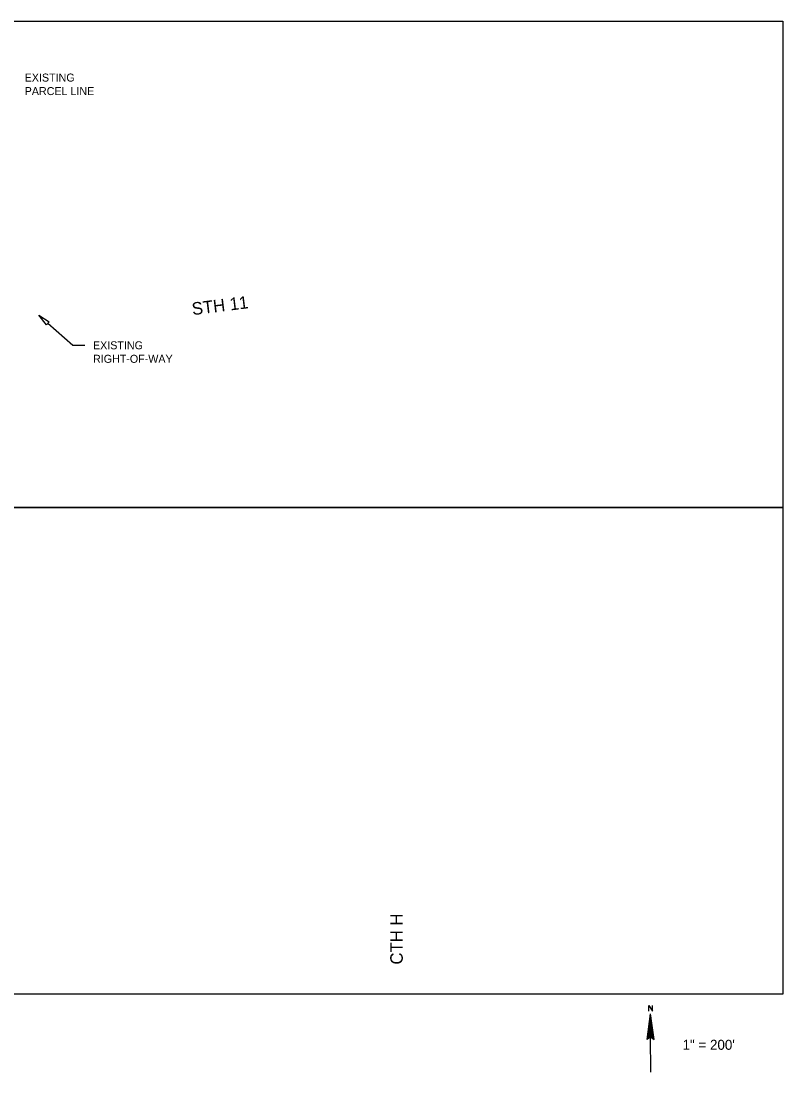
# Model space of a CAD drawing. Extents: x 0.3 to 16.7, y 0.2 to 10.7.
# Drawn here: x 9.12 to 16.74, y 0.21 to 10.72 of the extents above; entities that cross this region are included whole.
import ezdxf

# ---------------------------------------------------------------- set-up
doc = ezdxf.new("R2010")
doc.units = 0
doc.layers.add('P_Impacts_Assumed', color=7, linetype='Continuous')
doc.layers.add('PLT_Sheet_Info', color=7, linetype='Continuous')

# ---------------------------------------------------------------- blocks, each defined once
blk = doc.blocks.new('N')
for q in [(0, 117.4), (0, 117.3)]:
    blk.add_line((0, 0), q)
for points in [[(-5.4, 202.3), (-5.4, 222), (7.4, 202.3), (7.4, 222)], [(0, 117.4), (-11.5, 108.7), (0, 193.5)], [(-9.9, 111.3), (0, 187.8), (-8.2, 112.6), (-6.4, 114.1), (-0.1, 180.3), (-4.8, 115.5), (-3, 117.2), (-0.1, 170.8), (-1, 118.3)], [(0, 117.4), (11.5, 108.7), (0, 193.5)], [(10.3, 111.3), (0.3, 187.8), (8.5, 112.6), (6.7, 114.1), (0.4, 180.3), (5.1, 115.5), (3.4, 117.2), (0.4, 170.8), (1.4, 118.3)]]:
    blk.add_lwpolyline(points)

msp = doc.modelspace()

# ---------------------------------------------------------------- linework, layer by layer
at = {"layer": 'P_Impacts_Assumed'}
for points in [[(0.346, 10.718), (16.742, 10.718), (16.742, 5.854), (0.346, 5.854)], [(0.346, 5.854), (16.742, 5.854), (16.742, 0.991), (0.346, 0.991)]]:
    msp.add_lwpolyline(points, close=True, dxfattribs=at)
at = {"layer": 'PLT_Sheet_Info'}
msp.add_lwpolyline([(9.378, 7.683), (9.301, 7.777), (9.405, 7.713)], close=True, dxfattribs=at)
for points in [[(9.392, 7.698), (9.643, 7.477)], [(9.643, 7.477), (9.763, 7.477)]]:
    msp.add_lwpolyline(points, dxfattribs=at)

# ---------------------------------------------------------------- block references
at = {"layer": 'PLT_Sheet_Info', "xscale": 0.003, "yscale": 0.003, "rotation": 0.3186844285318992}
msp.add_blockref('N', (15.42, 0.213), dxfattribs=at)

# ---------------------------------------------------------------- texts
at = {"layer": 'PLT_Sheet_Info'}
for s, height, p in [('EXISTING', 0.08, (9.161, 10.113)), ('PARCEL LINE', 0.08, (9.161, 9.978)), ('EXISTING', 0.08, (9.844, 7.437)), ('RIGHT-OF-WAY', 0.08, (9.844, 7.302)), ('1" = 200\'', 0.1, (15.738, 0.435))]:
    msp.add_text(s, height=height, dxfattribs=at).set_placement(p)
for s, rotation, p in [('STH 11', 7.083, (10.84, 7.778)), ('CTH H', 90, (12.941, 1.287))]:
    msp.add_text(s, height=0.125, rotation=rotation, dxfattribs=at).set_placement(p)

doc.saveas('drawing.dxf')
